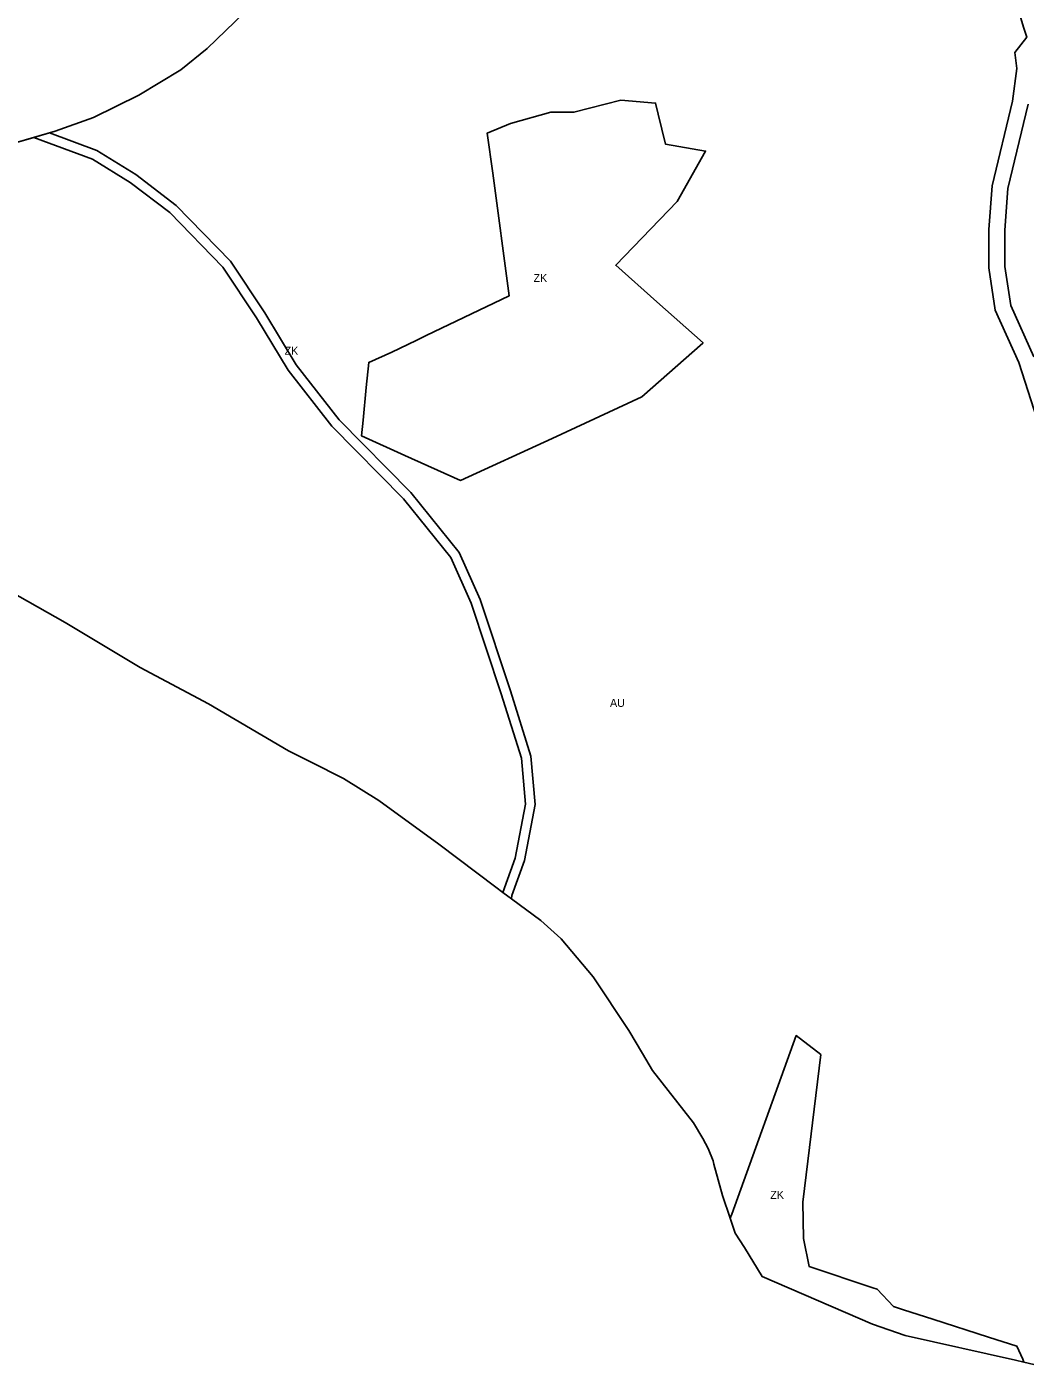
# Model space of a CAD drawing. Extents: x -521261 to -517465, y -1182764 to -1179456.
# Drawn here: x -520192 to -519568, y -1182342 to -1181503 of the extents above; entities that cross this region are included whole.
import ezdxf

# ---------------------------------------------------------------- set-up
doc = ezdxf.new("R2010")
doc.units = 0
for name, color, linetype in [('90710013', 7, 'Continuous'), ('90710023', 7, 'Continuous'), ('90750013', 7, 'Continuous'), ('90770013', 7, 'Continuous')]:
    doc.layers.add(name, color=color, linetype=linetype)

msp = doc.modelspace()

# ---------------------------------------------------------------- linework, layer by layer
at = {"layer": '90710013'}
for points in [[(-519797.665, -1181558.036), (-519793.159, -1181576.67), (-519768.095, -1181581.012), (-519785.79, -1181612.42), (-519824.21, -1181652.31), (-519798.441, -1181675.195), (-519769.609, -1181700.799), (-519769.78, -1181700.98), (-519807.95, -1181734.53), (-519863.92, -1181760.51), (-519921.32, -1181786.75), (-519955.98, -1181771.12), (-519983.1, -1181758.9), (-519982.16, -1181749.05), (-519980.12, -1181728.65), (-519978.55, -1181713), (-519964.15, -1181706.5), (-519948.91, -1181699.36), (-519942.73, -1181696.28), (-519890.89, -1181671.5), (-519900.98, -1181594.75), (-519904.659, -1181569.9), (-519890.05, -1181563.82), (-519864.72, -1181556.65), (-519850.41, -1181556.71), (-519820.94, -1181549.11), (-519799.35, -1181551.07)], [(-519889.089, -1182046.068), (-519889.277, -1182048.081), (-519894.736, -1182044.041), (-519887.022, -1182022.594), (-519880.546, -1181988.898), (-519883.119, -1181960.141), (-519895.774, -1181919.975), (-519914.652, -1181863.33), (-519927.195, -1181834.774), (-519956.778, -1181798.214), (-520001.689, -1181752.852), (-520028.846, -1181717.863), (-520048.653, -1181685.208), (-520069.674, -1181653.554), (-520102.926, -1181619.46), (-520127.621, -1181600.566), (-520151.18, -1181586.1), (-520187.89, -1181572.452), (-520178.188, -1181569.658), (-520148.54, -1181580.68), (-520124.219, -1181595.614), (-520098.934, -1181614.96), (-520064.986, -1181649.766), (-520043.587, -1181681.992), (-520023.894, -1181714.457), (-519997.171, -1181748.888), (-519952.302, -1181794.206), (-519922.025, -1181831.625), (-519909.048, -1181861.17), (-519890.066, -1181918.125), (-519877.201, -1181958.959), (-519874.494, -1181989.202), (-519881.218, -1182024.185)], [(-519749.55, -1182256.9), (-519752.766, -1182247.442), (-519751.72, -1182245.06), (-519711.36, -1182133.5), (-519696.09, -1182145.3), (-519707.29, -1182237.56), (-519706.82, -1182260.27), (-519703.24, -1182277.77), (-519663.51, -1182291.01), (-519660.94, -1182291.93), (-519650.66, -1182302.72), (-519644.33, -1182304.67), (-519626.06, -1182310.56), (-519591.16, -1182321.81), (-519573.45, -1182327.52), (-519569.7, -1182335.58), (-519569.087, -1182337.379), (-519574.39, -1182336.12), (-519643.28, -1182320.8), (-519663.67, -1182313.8), (-519732.68, -1182284.01), (-519743.73, -1182265.8)]]:
    msp.add_lwpolyline(points, close=True, dxfattribs=at)
at = {"layer": '90710023'}
for points in [[(-519551.44, -1181777.767), (-519572.226, -1181713.022), (-519587.026, -1181680.322), (-519590.97, -1181653.833), (-519590.98, -1181630.018), (-519588.994, -1181602.792), (-519576.305, -1181549.79), (-519573.589, -1181529.416), (-519574.763, -1181519.484), (-519567.26, -1181509.91)], [(-519566.46, -1181551.62), (-519579.08, -1181604.33), (-519580.98, -1181630.38), (-519580.97, -1181653.09), (-519577.34, -1181677.47), (-519562.88, -1181709.42)]]:
    msp.add_lwpolyline(points, dxfattribs=at)
at = {"layer": '90750013'}
for points in [[(-519560.34, -1181449.96), (-519569.85, -1181481.93), (-519571.73, -1181495.99), (-519569.38, -1181503.52), (-519567.26, -1181509.91), (-519574.763, -1181519.484), (-519573.589, -1181529.416), (-519576.305, -1181549.79), (-519588.994, -1181602.792), (-519590.98, -1181630.018), (-519590.97, -1181653.833), (-519587.026, -1181680.322), (-519572.226, -1181713.022), (-519551.44, -1181777.767)], [(-519550.42, -1182341.81), (-519569.087, -1182337.379), (-519569.7, -1182335.58), (-519573.45, -1182327.52), (-519591.16, -1182321.81), (-519626.06, -1182310.56), (-519644.33, -1182304.67), (-519650.66, -1182302.72), (-519660.94, -1182291.93), (-519663.51, -1182291.01), (-519703.24, -1182277.77), (-519706.82, -1182260.27), (-519707.29, -1182237.56), (-519696.09, -1182145.3), (-519711.36, -1182133.5), (-519751.72, -1182245.06), (-519752.766, -1182247.442), (-519757.57, -1182233.31), (-519762.82, -1182213.81), (-519763.37, -1182211.75), (-519766.48, -1182203.95), (-519769.71, -1182197.76), (-519775.64, -1182188.05), (-519801.31, -1182155.31), (-519807.53, -1182144.66), (-519816.08, -1182130.34), (-519838.32, -1182096.69), (-519858.25, -1182072.99), (-519858.466, -1182072.797), (-519871.12, -1182061.52), (-519889.277, -1182048.081), (-519889.277, -1182048.081), (-519889.089, -1182046.068), (-519881.218, -1182024.185), (-519874.494, -1181989.202), (-519877.201, -1181958.959), (-519890.066, -1181918.125), (-519909.048, -1181861.17), (-519922.025, -1181831.625), (-519952.302, -1181794.206), (-519997.171, -1181748.888), (-520023.894, -1181714.457), (-520043.587, -1181681.992), (-520064.986, -1181649.766), (-520098.934, -1181614.96), (-520124.219, -1181595.614), (-520148.54, -1181580.68), (-520178.188, -1181569.658), (-520174.55, -1181568.61), (-520150.55, -1181560.01), (-520122.34, -1181546.18), (-520096.12, -1181530.34), (-520079.5, -1181516.84), (-520056.39, -1181494.56)], [(-519562.88, -1181709.42), (-519577.34, -1181677.47), (-519580.97, -1181653.09), (-519580.98, -1181630.38), (-519579.08, -1181604.33), (-519566.46, -1181551.62)], [(-520208.16, -1181578.29), (-520187.89, -1181572.452), (-520151.18, -1181586.1), (-520127.621, -1181600.566), (-520102.926, -1181619.46), (-520069.674, -1181653.554), (-520048.653, -1181685.208), (-520028.846, -1181717.863), (-520001.689, -1181752.852), (-519956.778, -1181798.214), (-519927.195, -1181834.774), (-519914.652, -1181863.33), (-519895.774, -1181919.975), (-519883.119, -1181960.141), (-519880.546, -1181988.898), (-519887.022, -1182022.594), (-519894.736, -1182044.041), (-519899.25, -1182040.7), (-519934.82, -1182013.99), (-519972.21, -1181986.63), (-519994.4, -1181972.81), (-520014.65, -1181962.59), (-520028.82, -1181955.61), (-520078.63, -1181926.25), (-520121.36, -1181903.51), (-520168.26, -1181875.49), (-520220.41, -1181846.07)]]:
    msp.add_lwpolyline(points, dxfattribs=at)
msp.add_lwpolyline([(-519769.78, -1181700.98), (-519769.609, -1181700.799), (-519798.441, -1181675.195), (-519824.21, -1181652.31), (-519785.79, -1181612.42), (-519768.095, -1181581.012), (-519793.159, -1181576.67), (-519797.665, -1181558.036), (-519799.35, -1181551.07), (-519820.94, -1181549.11), (-519850.41, -1181556.71), (-519864.72, -1181556.65), (-519890.05, -1181563.82), (-519904.659, -1181569.9), (-519900.98, -1181594.75), (-519890.89, -1181671.5), (-519942.73, -1181696.28), (-519948.91, -1181699.36), (-519964.15, -1181706.5), (-519978.55, -1181713), (-519980.12, -1181728.65), (-519982.16, -1181749.05), (-519983.1, -1181758.9), (-519955.98, -1181771.12), (-519921.32, -1181786.75), (-519863.92, -1181760.51), (-519807.95, -1181734.53)], close=True, dxfattribs=at)
at = {"layer": '90770013'}
msp.add_lwpolyline([(-520056.39, -1181494.56), (-520079.5, -1181516.84), (-520096.12, -1181530.34), (-520122.34, -1181546.18), (-520150.55, -1181560.01), (-520174.55, -1181568.61), (-520208.16, -1181578.29)], dxfattribs=at)

# ---------------------------------------------------------------- texts
at = {"layer": '90710013'}
for p in [(-519875.597, -1181662.789), (-520031.192, -1181708.211), (-519727.636, -1182235.439)]:
    msp.add_text('ZK', height=5, rotation=360, dxfattribs=at).set_placement(p)
at = {"layer": '90750013'}
msp.add_text('AU', height=5, rotation=360, dxfattribs=at).set_placement((-519827.804, -1181928.173))

doc.saveas('drawing.dxf')
